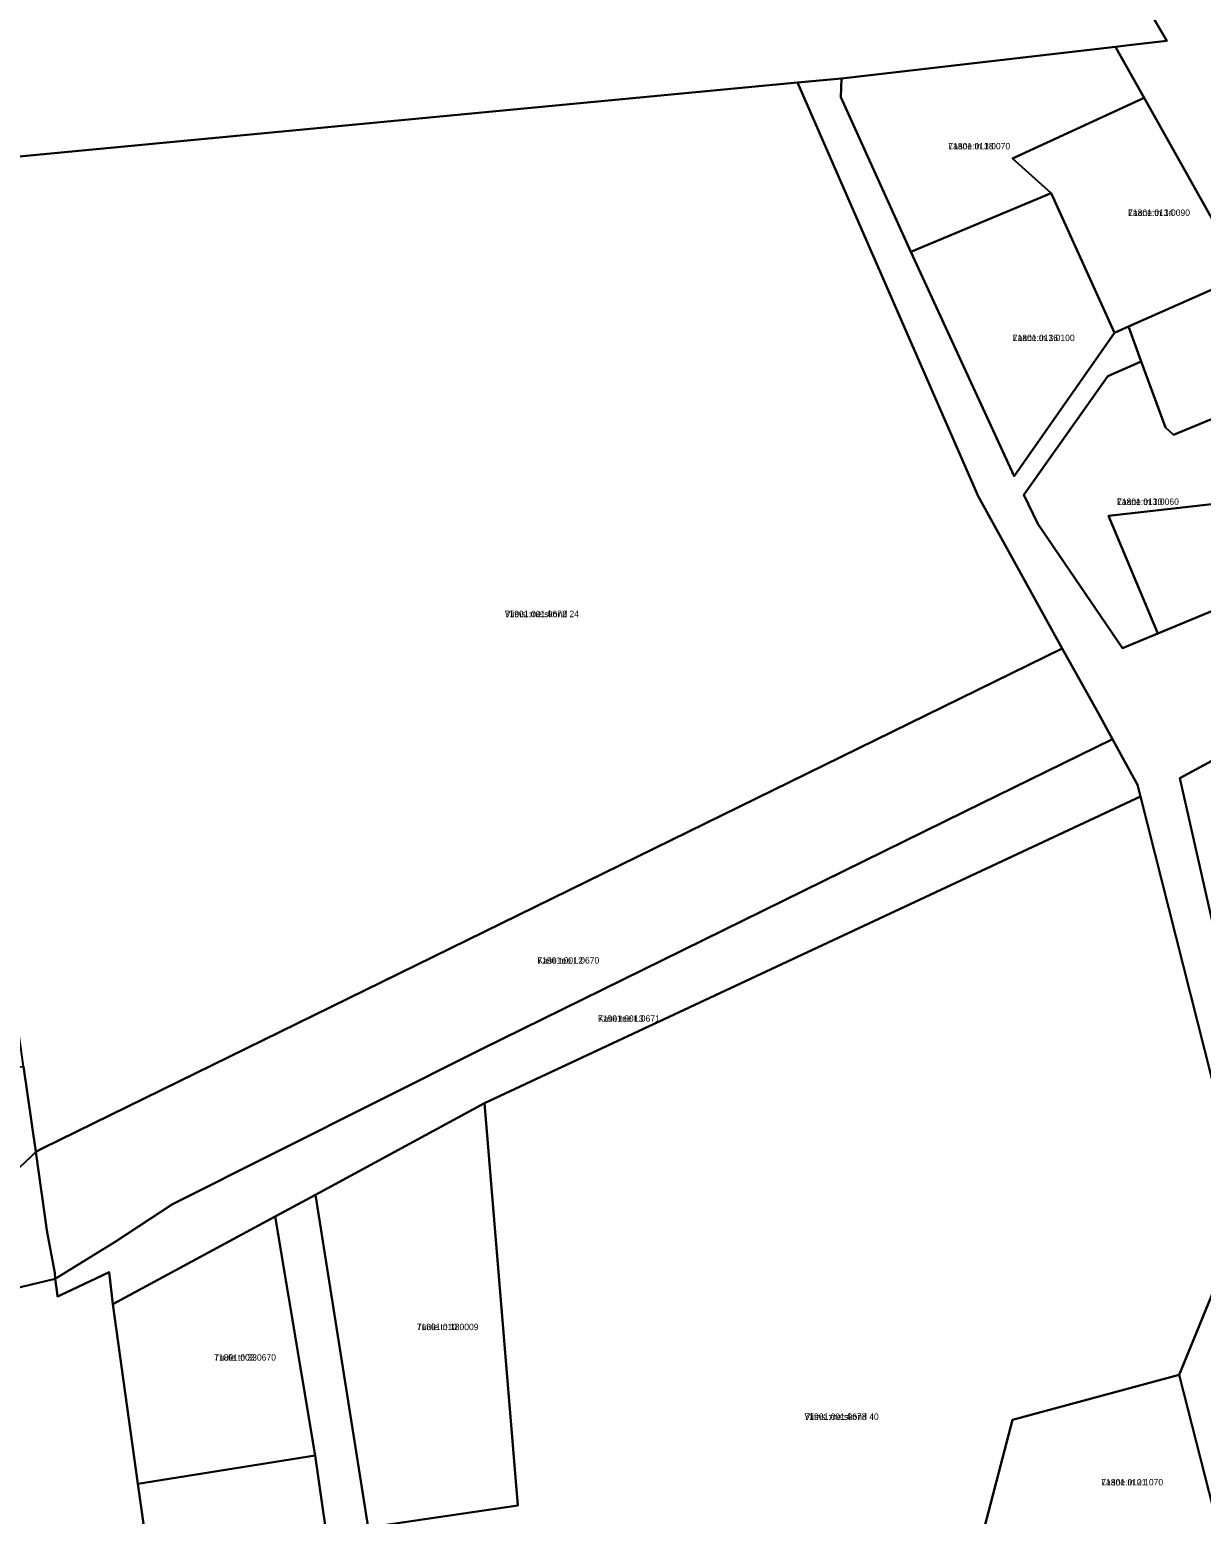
# Model space of a CAD drawing. Extents: x 529768 to 552006, y 6562269 to 6580975.
# Drawn here: x 537460.7 to 537735.3, y 6574791.4 to 6575139.4 of the extents above; entities that cross this region are included whole.
import ezdxf

# ---------------------------------------------------------------- set-up
doc = ezdxf.new("R2010")
doc.units = 0
for name, color, linetype in [('L_AADRESS', 7, 'Continuous'), ('PIIR', 7, 'Continuous'), ('TUNNUS', 7, 'Continuous')]:
    doc.layers.add(name, color=color, linetype=linetype)

msp = doc.modelspace()

# ---------------------------------------------------------------- linework, layer by layer
at = {"layer": 'PIIR'}
for points in [[(537310.82, 6575418.78), (537492.34, 6575439.76), (537502.72, 6575440.96), (537560.93, 6575371.07), (537580.43, 6575352.07), (537591.72, 6575339.39), (537605.65, 6575325.41), (537625.43, 6575296.8), (537664.03, 6575258.47), (537672.95, 6575249.61), (537681.39, 6575235.68), (537695.99, 6575202.65), (537718.28, 6575152.24), (537727.22, 6575136.84), (537718.33, 6575135.79), (537715.18, 6575135.41), (537650.95, 6575127.99), (537640.69, 6575127.02), (537429.37, 6575106.95)], [(537877.38, 6574790.27), (537877.44, 6574804.07), (537875.56, 6574871.37), (537866.76, 6574877.46), (537856.17, 6574871.76), (537832.47, 6574895.6), (537817.25, 6574925.17), (537812.88, 6574935.9), (537800.84, 6574964.08), (537787.82, 6574995.05), (537781.86, 6575021.43), (537771.25, 6575042.48), (537762.35, 6575055.48), (537745.3, 6575081.84), (537721.93, 6575123.45), (537716.1, 6575133.86), (537715.18, 6575135.41), (537718.33, 6575135.79), (537727.22, 6575136.84), (537718.28, 6575152.24)], [(537739.46, 6574887.08), (537721.06, 6574959.69), (537720.36, 6574962.42), (537716.82, 6574968.82), (537714.48, 6574973.14), (537711.11, 6574979.29), (537702.71, 6574994.4), (537683.04, 6575030.08), (537640.69, 6575127.02), (537650.95, 6575127.99), (537650.81, 6575123.61), (537667.26, 6575087.34), (537691.46, 6575034.79), (537715.01, 6575068.35), (537718.25, 6575069.88), (537721.22, 6575061.64), (537713.43, 6575058.2), (537693.76, 6575030.37), (537697.03, 6575023.57), (537716.85, 6574994.41), (537725.15, 6574997.87), (537781.86, 6575021.43)], [(537746.19, 6574972.53), (537730.27, 6574963.99), (537738.05, 6574929.75)], [(537447.39, 6574862.49), (537461.1, 6574875.4), (537462.1, 6574876.39), (537463.52, 6574866.41), (537464.71, 6574858), (537464.95, 6574856.68), (537466.54, 6574848), (537466.66, 6574846.6), (537456.9, 6574844.24)], [(537531.69, 6574776.86), (537527.63, 6574805.18), (537518.26, 6574861.23), (537527.67, 6574866.31), (537540.02, 6574788.31)], [(537740.19, 6574784.56), (537730.17, 6574824.12), (537744.59, 6574859.46)], [(537392.27, 6574743.64), (537456.9, 6574844.24), (537466.66, 6574846.6), (537467.03, 6574843.88), (537467.22, 6574842.49), (537469.04, 6574843.33), (537479.29, 6574848.14), (537480.18, 6574840.63), (537486.06, 6574798.57), (537490.03, 6574770.53)]]:
    msp.add_lwpolyline(points, dxfattribs=at)
for points in [[(537715.18, 6575135.41), (537716.1, 6575133.86), (537721.93, 6575123.45), (537691.05, 6575109.25), (537700.13, 6575101.13), (537667.26, 6575087.34), (537650.81, 6575123.61), (537650.95, 6575127.99)], [(537446.69, 6574993.25), (537446.29, 6574995.88), (537438.17, 6575049.78), (537437.41, 6575054.73), (537429.62, 6575105.01), (537429.37, 6575106.95), (537640.69, 6575127.02), (537683.04, 6575030.08), (537702.71, 6574994.4), (537463.63, 6574877.14), (537462.1, 6574876.39), (537459.26, 6574896.37), (537455.72, 6574921.31), (537454.55, 6574929.59), (537454.23, 6574934.58), (537452.8, 6574946.22), (537449.74, 6574971.11), (537447.61, 6574988.37)], [(537715.01, 6575068.35), (537700.13, 6575101.13), (537691.05, 6575109.25), (537721.93, 6575123.45), (537745.3, 6575081.84), (537718.25, 6575069.88)], [(537700.13, 6575101.13), (537715.01, 6575068.35), (537691.46, 6575034.79), (537667.26, 6575087.34)], [(537726.91, 6575046.15), (537721.22, 6575061.64), (537718.25, 6575069.88), (537745.3, 6575081.84), (537762.35, 6575055.48), (537745.6, 6575046.36), (537743.96, 6575050.67), (537728.83, 6575044.46)], [(537726.91, 6575046.15), (537728.83, 6575044.46), (537743.96, 6575050.67), (537745.6, 6575046.36), (537762.35, 6575055.48), (537771.25, 6575042.48), (537751.6, 6575029.77), (537713.53, 6575025.44), (537725.15, 6574997.87), (537716.85, 6574994.41), (537697.03, 6575023.57), (537693.76, 6575030.37), (537713.43, 6575058.2), (537721.22, 6575061.64)], [(537713.53, 6575025.44), (537751.6, 6575029.77), (537771.25, 6575042.48), (537781.86, 6575021.43), (537725.15, 6574997.87)], [(537463.63, 6574877.14), (537702.71, 6574994.4), (537711.11, 6574979.29), (537714.48, 6574973.14), (537679.76, 6574956.08), (537566.75, 6574900.55), (537494.13, 6574864.08), (537480.69, 6574855.27), (537469.33, 6574848.24), (537466.66, 6574846.6), (537466.54, 6574848), (537464.95, 6574856.68), (537464.71, 6574858), (537463.52, 6574866.41), (537462.1, 6574876.39)], [(537467.03, 6574843.88), (537466.66, 6574846.6), (537469.33, 6574848.24), (537480.69, 6574855.27), (537494.13, 6574864.08), (537566.75, 6574900.55), (537679.76, 6574956.08), (537714.48, 6574973.14), (537716.82, 6574968.82), (537720.36, 6574962.42), (537721.06, 6574959.69), (537567.33, 6574887.8), (537527.67, 6574866.31), (537518.26, 6574861.23), (537480.18, 6574840.63), (537479.29, 6574848.14), (537469.04, 6574843.33), (537467.22, 6574842.49)], [(537746.19, 6574972.53), (537762.37, 6574942.71), (537756.62, 6574939.57), (537738.05, 6574929.75), (537730.27, 6574963.99)], [(537575.1, 6574793.51), (537567.33, 6574887.8), (537721.06, 6574959.69), (537739.46, 6574887.08), (537744.59, 6574859.46), (537730.17, 6574824.12), (537691.03, 6574813.55), (537680.26, 6574772.23), (537701.22, 6574747.22), (537673.77, 6574708.6), (537642.67, 6574704.19), (537621.56, 6574706.93), (537618.19, 6574702.52), (537588.02, 6574714.43), (537548.93, 6574726.02), (537540.02, 6574788.31)], [(537416.98, 6574855.26), (537411.82, 6574892.33), (537456.29, 6574896.1), (537459.26, 6574896.37), (537462.1, 6574876.39), (537461.1, 6574875.4), (537447.39, 6574862.49)], [(537527.67, 6574866.31), (537567.33, 6574887.8), (537575.1, 6574793.51), (537540.02, 6574788.31)], [(537527.63, 6574805.18), (537486.06, 6574798.57), (537480.18, 6574840.63), (537518.26, 6574861.23)], [(537730.17, 6574824.12), (537740.19, 6574784.56), (537680.26, 6574772.23), (537691.03, 6574813.55)], [(537486.06, 6574798.57), (537527.63, 6574805.18), (537531.69, 6574776.86), (537490.03, 6574770.53)]]:
    msp.add_lwpolyline(points, close=True, dxfattribs=at)

# ---------------------------------------------------------------- texts
at = {"layer": 'L_AADRESS'}
for s, p in [('Laane tn 38', (537676.02, 6575111.38)), ('Laane tn 34', (537718.17, 6575095.78)), ('Laane tn 36', (537691.13, 6575066.43)), ('Laane tn 30', (537715.57, 6575028.03)), ('Viimsi metskond 24', (537572.05, 6575001.71)), ('Kase tee L2', (537579.69, 6574920.5)), ('Kase tee L3', (537593.89, 6574906.88)), ('Tuule tn 18', (537551.39, 6574834.58)), ('Tuule tn 33', (537503.91, 6574827.44)), ('Viimsi metskond 40', (537642.31, 6574813.55)), ('Laane tn 21', (537711.88, 6574798.18))]:
    msp.add_text(s, height=1.5, dxfattribs=at).set_placement(p)
at = {"layer": 'TUNNUS'}
for s, p in [('71801:011:0070', (537676.02, 6575111.38)), ('71801:011:0090', (537718.17, 6575095.78)), ('71801:011:0100', (537691.13, 6575066.43)), ('71801:011:0060', (537715.57, 6575028.03)), ('71901:001:0672', (537572.05, 6575001.71)), ('71901:001:0670', (537579.69, 6574920.5)), ('71901:001:0671', (537593.89, 6574906.88)), ('71801:010:0009', (537551.39, 6574834.58)), ('71801:003:0670', (537503.91, 6574827.44)), ('71901:001:0673', (537642.31, 6574813.55)), ('71801:010:1070', (537711.88, 6574798.18))]:
    msp.add_text(s, height=1.5, dxfattribs=at).set_placement(p)

doc.saveas('drawing.dxf')
